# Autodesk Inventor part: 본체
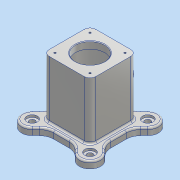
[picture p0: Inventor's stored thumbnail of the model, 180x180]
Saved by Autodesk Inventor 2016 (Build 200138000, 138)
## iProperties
Created: 2019-11
Part Number: 본체
Material: 알루미늄 6061
Document SubType Name: Modeling
Designer: user
Density: 2.7 g/cm^3
Appearance: 알루미늄 - 평지
Mass: 1076.28 g
Surface Area: 879.964 cm^2
Volume: 398.62 cm^3
Author: user
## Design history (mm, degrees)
sketch "스케치2"
  geometry: L1 (-49, 49)-(49, 49); L2 (49, 49)-(49, -49); L3 (49, -49)-(-49, -49); L4 (-49, -49)-(-49, 49); L5 (-49, 49)-(49, -49); L6 (49, 49)-(-49, -49); L7 (-49.497, -49.497)-(49.497, 49.497); L8 (-36.77, -62.225)-(62.225, 36.77); L9 (36.77, 62.225)-(-62.225, -36.77); L10 (49.497, -49.497)-(-49.497, 49.497); L11 (62.225, -36.77)-(-36.77, 62.225); L12 (-62.225, 36.77)-(36.77, -62.225); A1 r 70 centre (0, 0) between (49.497, 49.497) and (-49.497, 49.497); A2 r 18 centre (-49.497, -49.497) between (-62.225, -36.77) and (-36.77, -62.225); A3 r 18 centre (49.497, 49.497) between (62.225, 36.77) and (36.77, 62.225); A4 r 18 centre (49.497, -49.497) between (36.77, -62.225) and (62.225, -36.77); A5 r 18 centre (-49.497, 49.497) between (-36.77, 62.225) and (-62.225, 36.77); 2 further points
  constraints: 28 end point, 10 point on circle, 8 tangent, 6 midpoint, 5 centre point, 4 parallel, 2 point on line, 1 coincident, 1 horizontal, 1 perpendicular
  dimensions: "d0" = 98 distance of L2.end L3.end; "d1" = 98 distance of L1.end L2.end; "d2" = 140 diameter of A1; "d3" = 36 diameter of A3; "d4" = 36 diameter of A5
extrude "돌출1" new body sketch "스케치2" distance "d5" = 12; taper "d6" = 0 deg
sketch "스케치4"
  geometry: A1 r 18 centre (-49.497, 49.497) between (-36.77, 62.225) and (-62.225, 36.77) reference; A2 r 18 centre (49.497, 49.497) between (62.225, 36.77) and (36.77, 62.225) reference; A3 r 18 centre (49.497, -49.497) between (36.77, -62.225) and (62.225, -36.77) reference; A4 r 18 centre (-49.497, -49.497) between (-62.225, -36.77) and (-36.77, -62.225) reference; 5 further points
  constraints: 4 coincident
hole "구멍2" sketch "스케치4" at (-49.497, 49.497), (49.497, 49.497), (49.497, -49.497), (-49.497, -49.497) diameter "d14" = 10; stored, may be unused: countersink angle "d18" = 90 deg, drill point angle "d20" = 118 deg; dims "d15" = 6, "d16" = 18, "d17" = 4, "d19" = 8
sketch "스케치5"
  geometry: L1 (-40, 40)-(40, 40); L2 (40, 40)-(40, -40); L3 (40, -40)-(-40, -40); L4 (-40, -40)-(-40, 40); L5 (-40, 40)-(40, -40); L6 (40, 40)-(-40, -40); 1 further point
  constraints: 12 end point, 2 midpoint, 2 parallel, 1 horizontal, 1 perpendicular
  dimensions: "d21" = 80 distance of L2.end L3.end; "d22" = 80 distance of L1.end L2.end
extrude "돌출2" join sketch "스케치5" distance "d23" = 98; taper "d24" = 0 deg
node "작업 평면1"
sketch "스케치6"
  geometry: C1 r 20 at (0, 61); 1 further point
  constraints: 1 centre point, 1 vertical alignment
  dimensions: "d26" = 61 distance of point (0, 0) C1.centre; "d27" = 40 diameter of C1
extrude "돌출3" join sketch "스케치6" stored distance "d28" = 98; taper "d29" = 0 deg
node "작업 평면2"
sketch "스케치8"
  geometry: 2 further points
  constraints: 1 vertical alignment
  dimensions: "d31" = 61 distance of point (0, 61) point (0, 0)
hole "구멍3" sketch "스케치8" at (0, 61) diameter "d32" = 25; stored, may be unused: countersink angle "d36" = 90 deg, drill point angle "d38" = 118 deg; dims "d33" = 6, "d34" = 30, "d35" = 8, "d37" = 55
sketch "스케치9"
  geometry: C1 r 25 at (0, 0); 1 further point
  constraints: 1 centre point, 1 coincident
  dimensions: "d39" = 50 diameter of C1
extrude "돌출4" cut sketch "스케치9" distance "d40" = 12; taper "d41" = 0 deg
sketch "스케치10"
  geometry: C1 r 35 at (0, 0); 1 further point
  constraints: 1 centre point, 1 coincident
  dimensions: "d42" = 70 diameter of C1
extrude "돌출5" cut sketch "스케치10" distance "d43" = 86; taper "d44" = 0 deg
sketch "스케치11"
  geometry: C1 r 25 at (0, 0); 1 further point
  constraints: 1 centre point, 1 coincident
  dimensions: "d45" = 50 diameter of C1
extrude "돌출6" cut sketch "스케치11" distance "d46" = 12; taper "d47" = 0 deg
sketch "스케치12"
  geometry: L1 (30, -30)-(-30, -30); L2 (-30, -30)-(-30, 30); L3 (-30, 30)-(30, 30); L4 (30, 30)-(30, -30); L5 (30, -30)-(-30, 30); L6 (-30, -30)-(30, 30); 2 further points
  constraints: 12 end point, 2 midpoint, 2 parallel, 1 coincident, 1 horizontal, 1 perpendicular
  dimensions: "d48" = 60 distance of L2.end L3.end; "d49" = 60 distance of L1.end L2.end
hole "구멍4" sketch "스케치12" at (30, -30) diameter "d50" = 3.242; stored, may be unused: countersink angle "d54" = 90 deg, drill point angle "d56" = 118 deg; dims "d51" = 8, "d52" = 30, "d53" = 8, "d55" = 10
node "작업 평면3"
fillet "모깎기1" dims "d61" = 10
fillet "모깎기2" dims "d62" = 25
fillet "모깎기3" dims "d63" = 3
chamfer "모따기1" distance "d64" = 1; stored, may be unused: second distance "d65" = 2, angle "d66" = 45 deg
fillet "모깎기4" dims "d67" = 3
sketch "스케치13"
  geometry: L1 (60, -98)-(0, -98) reference; L2 (16.811, 12)-(43.189, 12) reference; 3 further points
  constraints: 1 midpoint, 1 vertical alignment, 1 other
  dimensions: "d68" = 10 distance from line of L1 point (30, -88)
feature "엠보싱1" sketch "스케치13" dims "d0" = 98, "d1" = 98, "d2" = 140, "d3" = 36, "d4" = 36, "d69" = 0.5, "d70" = 0
fillet "모깎기5" dims "d71" = 3
fillet "모깎기6" dims "d72" = 3
node "솔리드1"
pattern_circular "원형 패턴1" dims angle "d58" = 360 deg
mirror "대칭1"
other parameters: "d25" = 55, "d30" = 55, "d60" = 55
